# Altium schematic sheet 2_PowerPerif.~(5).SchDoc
size 414 x 293 mm; SheetNumber: 2; SheetTotal: 4
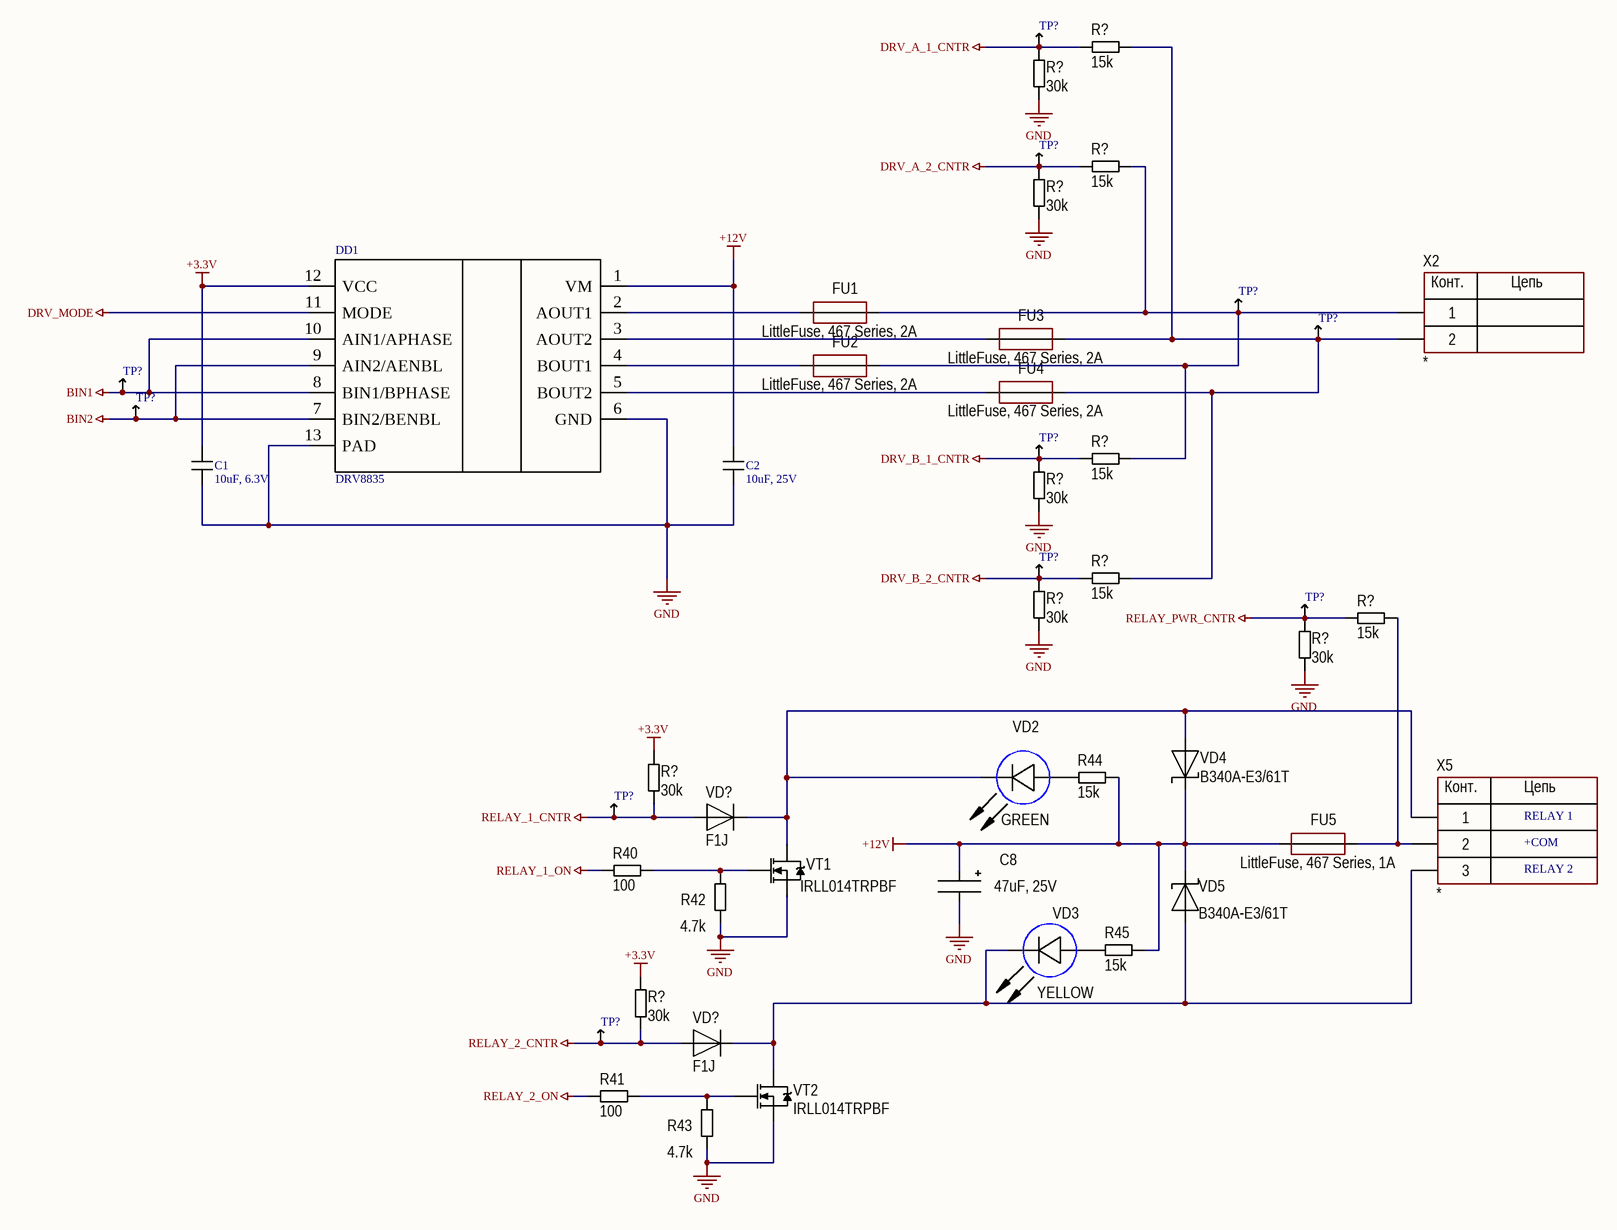
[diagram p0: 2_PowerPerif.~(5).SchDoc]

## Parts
(Parts that share a designator on the sheet are numbered #1, #2 ... from top to bottom, then left to right.)
C1  10uF, 6.3V  [C_0603]
C2  10uF, 25V  [C_0603]
C8  47uF, 25V  [D8C3.2H12]
DD1  DRV8835  [WSON12]
FU1  LittleFuse, 467 Series, 2A  [CH0603F]
FU2  LittleFuse, 467 Series, 2A  [CH0603F]
FU3  LittleFuse, 467 Series, 2A  [CH0603F]
FU4  LittleFuse, 467 Series, 2A  [CH0603F]
FU5  LittleFuse, 467 Series, 1A  [CH0603F]
R40  100  [CH0805R]
R41  100  [CH0805R]
R42  4.7k  [CH0805R]
R43  4.7k  [CH0805R]
R44  15k  [CH0805R]
R45  15k  [CH0805R]
R?#1  15k  [CH0805R]
R?#2  30k  [CH0805R]
R?#3  15k  [CH0805R]
R?#4  30k  [CH0805R]
R?#5  15k  [CH0805R]
R?#6  30k  [CH0805R]
R?#7  15k  [CH0805R]
R?#8  15k  [CH0805R]
R?#9  30k  [CH0805R]
R?#10  30k  [CH0805R]
R?#11  30k  [CH0805R]
R?#12  30k  [CH0805R]
TP?#1  TestPoint  (value not drawn)
TP?#2  TestPoint  (value not drawn)
TP?#3  TestPoint  (value not drawn)
TP?#4  TestPoint  (value not drawn)
TP?#5  TestPoint  (value not drawn)
TP?#6  TestPoint  (value not drawn)
TP?#7  TestPoint  (value not drawn)
TP?#8  TestPoint  (value not drawn)
TP?#9  TestPoint  (value not drawn)
TP?#10  TestPoint  (value not drawn)
TP?#11  TestPoint  (value not drawn)
VD2  GREEN  [CH0603LB]
VD3  YELLOW  [CH0603LB]
VD4  B340A-E3/61T  [SMA]
VD5  B340A-E3/61T  [SMA]
VD?#1  F1J  [SOD123F]
VD?#2  F1J  [SOD123F]
VT1  IRLL014TRPBF  [SOT223]
VT2  IRLL014TRPBF  [SOT223]
X2  *  [CON: CWF-2]
X5  *  [CON: 300-03P-5.0]

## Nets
+3.3V: C1.2 DD1.12(VCC) R?#11.2 R?#12.2
+12V: C2.2 C8.1 DD1.1(VM) FU5.1 R44.2 R45.2 VD4.2 VD5.2
BIN1: DD1.8(BIN1/BPHASE) DD1.10(AIN1/APHASE) TP?#5.0
BIN2: DD1.7(BIN2/BENBL) DD1.9(AIN2/AENBL) TP?#6.0
DRV_A_1_CNTR: R?#1.1 R?#2.2 TP?#1.0
DRV_A_2_CNTR: R?#3.1 R?#4.2 TP?#2.0
DRV_B_1_CNTR: R?#5.1 R?#6.2 TP?#7.0
DRV_B_2_CNTR: R?#7.1 R?#9.2 TP?#8.0
DRV_MODE: DD1.11(MODE)
GND: C1.1 C2.1 C8.2 DD1.6(GND) DD1.13(PAD) R42.1 R43.1 R?#2.1 R?#4.1 R?#6.1 R?#9.1 R?#10.1 VT1.3(S) VT2.3(S)
RELAY_1_CNTR: R?#11.1 TP?#10.0 VD?#1.1
RELAY_1_ON: R40.2
RELAY_2_CNTR: R?#12.1 TP?#11.0 VD?#2.1
RELAY_2_ON: R41.2
RELAY_PWR_CNTR: R?#8.1 R?#10.2 TP?#9.0
NetDD1_2: DD1.2(AOUT1) FU1.1
NetDD1_3: DD1.3(AOUT2) FU3.1
NetDD1_4: DD1.4(BOUT1) FU2.1
NetDD1_5: DD1.5(BOUT2) FU4.1
NetFU1_2: FU1.2 FU2.2 R?#3.2 R?#5.2 TP?#3.0 X2.1
NetFU3_2: FU3.2 FU4.2 R?#1.2 R?#7.2 TP?#4.0 X2.2
NetFU5_2: FU5.2 R?#8.2 X5.2
NetR40_1: R40.1 R42.2 VT1.1(G)
NetR41_1: R41.1 R43.2 VT2.1(G)
NetR44_1: R44.1 VD2.1(A)
NetR45_1: R45.1 VD3.1(A)
NetVD2_2: VD2.2(C) VD4.1 VD?#1.2 VT1.2(D) X5.1
NetVD3_2: VD3.2(C) VD5.1 VD?#2.2 VT2.2(D) X5.3

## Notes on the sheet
- RELAY 1
- +COM
- RELAY 2

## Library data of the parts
C1 C2 = C_SMD
C8 = AlumCap
DD1 = DRV8835: Driver
FU1-FU5 = Fuse
R40-R45 R?#1-R?#12 = Resistor
VD2 VD3 = LED_1
VD4 VD5 = Diod Schottky
VD?#1 VD?#2 = Diod
VT1 VT2 = N-chanel: Mosfet
X2 = 2-Connector
X5 = 3-Connector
